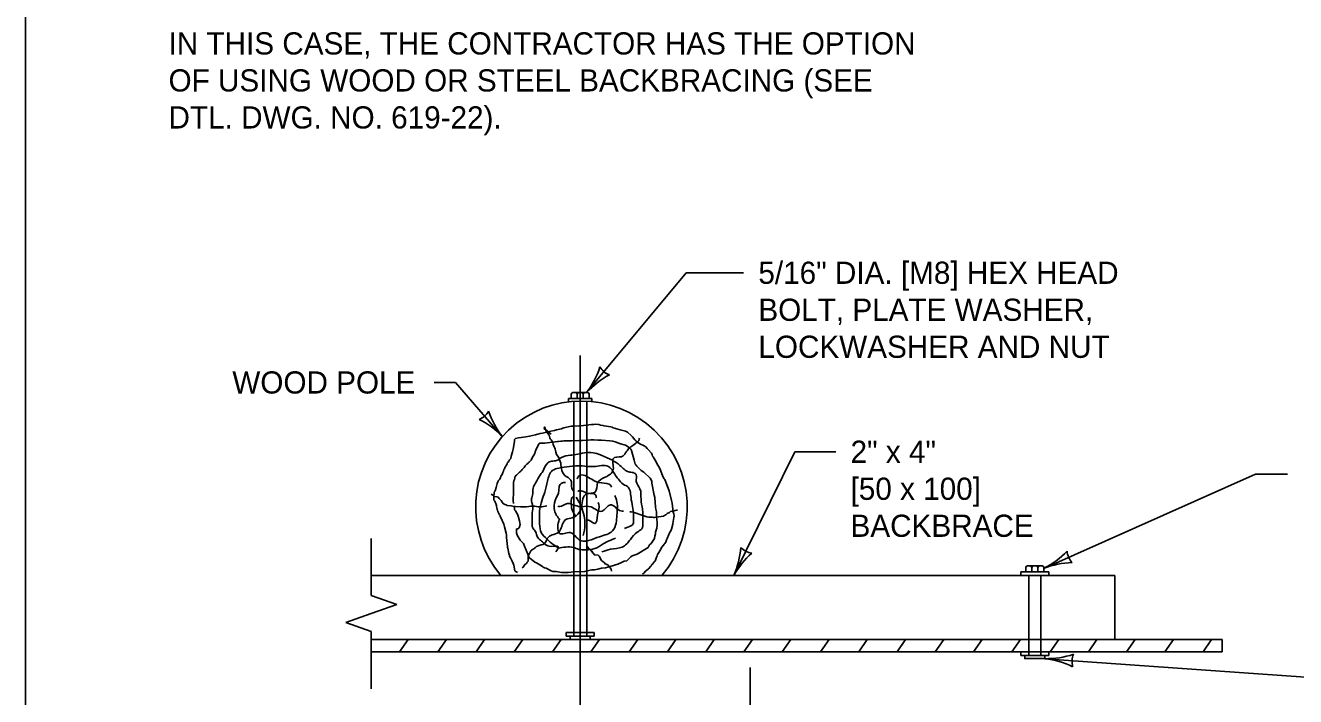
# Model space of a CAD drawing. Extents: x 49991.4 to 50021, y 49987.6 to 50011.4.
# Drawn here: x 50000.336 to 50003.769, y 50005.439 to 50007.252 of the extents above; entities that cross this region are included whole.
import ezdxf

# ---------------------------------------------------------------- set-up
doc = ezdxf.new("R2010")
doc.units = 0
for name, color, linetype in [('Level 1', 7, 'Continuous'), ('Level 2', 7, 'Continuous'), ('Level 3', 7, 'Continuous'), ('Level 4', 7, 'Continuous'), ('Level 5', 7, 'Continuous'), ('Level 6', 7, 'Continuous')]:
    doc.layers.add(name, color=color, linetype=linetype)

msp = doc.modelspace()

# ---------------------------------------------------------------- linework, layer by layer
at = {"layer": 'Level 1'}
for p, q in [((50001.8109, 50006.2555), (50001.8109, 50006.2437)), ((50001.8555, 50006.2601), (50001.8155, 50006.2601)), ((50001.8273, 50006.2601), (50001.8273, 50006.2437)), ((50001.8436, 50006.2601), (50001.8436, 50006.2437)), ((50001.8598, 50006.2554), (50001.8598, 50006.2437)), ((50001.8036, 50006.2437), (50001.8672, 50006.2437)), ((50001.8036, 50006.2437), (50001.8036, 50006.2351)), ((50001.8672, 50006.2357), (50001.8672, 50006.2437)), ((50001.8393, 50005.951), (50001.8245, 50005.9776)), ((50003.0268, 50005.7755), (50003.102, 50005.7755)), ((50003.0268, 50005.7656), (50003.0268, 50005.7755)), ((50003.0398, 50005.7873), (50003.0398, 50005.7755)), ((50003.0844, 50005.7919), (50003.0444, 50005.7919)), ((50003.0562, 50005.7919), (50003.0562, 50005.7755)), ((50003.0725, 50005.7919), (50003.0725, 50005.7755)), ((50003.0887, 50005.7872), (50003.0887, 50005.7755)), ((50003.102, 50005.7656), (50003.102, 50005.7755)), ((50001.2707, 50005.7656), (50003.2808, 50005.7656)), ((50003.2808, 50005.7656), (50003.2808, 50005.593)), ((50001.7978, 50005.6116), (50001.7978, 50005.6015)), ((50001.873, 50005.6116), (50001.7978, 50005.6116)), ((50001.873, 50005.6015), (50001.7978, 50005.6015)), ((50001.873, 50005.6116), (50001.873, 50005.6015)), ((50001.2707, 50005.593), (50003.5711, 50005.593)), ((50001.3468, 50005.5599), (50001.37, 50005.593)), ((50001.4503, 50005.5599), (50001.4735, 50005.593)), ((50001.5537, 50005.5599), (50001.5769, 50005.593)), ((50001.6572, 50005.5599), (50001.6804, 50005.593)), ((50001.7607, 50005.5599), (50001.7839, 50005.593)), ((50001.8641, 50005.5599), (50001.8873, 50005.593)), ((50001.9676, 50005.5599), (50001.9908, 50005.593)), ((50002.071, 50005.5599), (50002.0942, 50005.593)), ((50002.1745, 50005.5599), (50002.1977, 50005.593)), ((50002.2779, 50005.5599), (50002.3011, 50005.593)), ((50002.3814, 50005.5599), (50002.4046, 50005.593)), ((50002.4848, 50005.5599), (50002.508, 50005.593)), ((50002.5883, 50005.5599), (50002.6115, 50005.593)), ((50002.6918, 50005.5599), (50002.715, 50005.593)), ((50002.7952, 50005.5599), (50002.8184, 50005.593)), ((50002.8987, 50005.5599), (50002.9219, 50005.593)), ((50003.0021, 50005.5599), (50003.0253, 50005.593)), ((50003.1056, 50005.5599), (50003.1288, 50005.593)), ((50003.209, 50005.5599), (50003.2322, 50005.593)), ((50003.3125, 50005.5599), (50003.3354, 50005.5925)), ((50003.4159, 50005.5599), (50003.4388, 50005.5925)), ((50003.5194, 50005.5599), (50003.5423, 50005.5925)), ((50003.5711, 50005.5599), (50003.5711, 50005.593)), ((50001.2707, 50005.5599), (50003.5711, 50005.5599)), ((50003.0268, 50005.5599), (50003.0268, 50005.5498)), ((50003.102, 50005.5498), (50003.0268, 50005.5498)), ((50003.102, 50005.5599), (50003.102, 50005.5498))]:
    msp.add_line(p, q, dxfattribs=at)
for points in [[(50008.6146, 50011.2628), (50000.3356, 50011.2628), (50000.3356, 50000.0624), (50008.6146, 50000.0624)], [(50001.8081, 50005.6015), (50001.8081, 50005.593), (50001.8627, 50005.593), (50001.8627, 50005.6015)], [(50003.0371, 50005.5498), (50003.0371, 50005.5413), (50003.0917, 50005.5413), (50003.0917, 50005.5498)]]:
    msp.add_lwpolyline(points, close=True, dxfattribs=at)
for points in [[(50001.6079, 50006.0034), (50001.6112, 50006.0141), (50001.6128, 50006.019), (50001.6145, 50006.0223), (50001.6169, 50006.0256), (50001.6202, 50006.0297), (50001.6211, 50006.0346), (50001.6243, 50006.0387), (50001.626, 50006.0444), (50001.6276, 50006.0477), (50001.6293, 50006.0526), (50001.6309, 50006.0543), (50001.6326, 50006.0592), (50001.6342, 50006.0608), (50001.6375, 50006.0674), (50001.6392, 50006.0707), (50001.6408, 50006.0723), (50001.6425, 50006.0748), (50001.6441, 50006.078), (50001.6474, 50006.0821), (50001.649, 50006.0887), (50001.6523, 50006.1002), (50001.654, 50006.1068), (50001.6573, 50006.1281), (50001.6581, 50006.133), (50001.6606, 50006.1363), (50001.6688, 50006.1379), (50001.6754, 50006.1387), (50001.6886, 50006.1404), (50001.6984, 50006.142), (50001.7149, 50006.1461), (50001.7174, 50006.1469), (50001.7207, 50006.1478), (50001.7273, 50006.1494), (50001.733, 50006.1502), (50001.7445, 50006.1535), (50001.7561, 50006.156), (50001.7659, 50006.1576), (50001.7717, 50006.1592), (50001.7799, 50006.1609), (50001.7849, 50006.1625), (50001.7882, 50006.1642), (50001.7915, 50006.165), (50001.803, 50006.1674), (50001.8112, 50006.1691), (50001.8195, 50006.1691), (50001.8326, 50006.1699), (50001.8442, 50006.1707), (50001.8656, 50006.174), (50001.8721, 50006.174), (50001.8771, 50006.1748), (50001.8853, 50006.174), (50001.8903, 50006.1724), (50001.8968, 50006.1715), (50001.9001, 50006.1699), (50001.9183, 50006.1674), (50001.9215, 50006.1666), (50001.9248, 50006.165), (50001.9438, 50006.1592), (50001.9578, 50006.156), (50001.9611, 50006.1543), (50001.9635, 50006.1527), (50001.9734, 50006.1445), (50001.9751, 50006.142), (50001.9767, 50006.1404), (50001.9833, 50006.1322), (50001.9866, 50006.1289), (50001.9907, 50006.1256), (50001.9981, 50006.1207), (50002.0063, 50006.1174), (50002.0129, 50006.1133), (50002.0162, 50006.1092), (50002.0195, 50006.1059), (50002.0277, 50006.0961), (50002.0302, 50006.092), (50002.031, 50006.0887), (50002.0327, 50006.0862), (50002.0409, 50006.0731), (50002.0442, 50006.0649), (50002.0475, 50006.06), (50002.0524, 50006.0502), (50002.0557, 50006.0403), (50002.0599, 50006.0313), (50002.0623, 50006.0272), (50002.064, 50006.0256), (50002.0714, 50006.0059), (50002.0755, 50005.9944), (50002.0821, 50005.9681), (50002.0837, 50005.9616), (50002.087, 50005.937), (50002.0887, 50005.9321), (50002.0895, 50005.9271), (50002.0887, 50005.9222), (50002.0854, 50005.9066), (50002.0854, 50005.9042), (50002.0821, 50005.891), (50002.0813, 50005.8886), (50002.0788, 50005.8837), (50002.0771, 50005.8812), (50002.0755, 50005.8787), (50002.0747, 50005.8763)], [(50001.7717, 50006.0924), (50001.7692, 50006.0994), (50001.7684, 50006.1035), (50001.7676, 50006.1068), (50001.7668, 50006.11), (50001.7651, 50006.1133), (50001.7627, 50006.1199), (50001.761, 50006.1248), (50001.7594, 50006.1289), (50001.7569, 50006.1322), (50001.7544, 50006.1355), (50001.7536, 50006.1379), (50001.7511, 50006.1453), (50001.747, 50006.1502), (50001.7445, 50006.1535), (50001.7437, 50006.156), (50001.7412, 50006.1609), (50001.7404, 50006.1633), (50001.7396, 50006.1674), (50001.7396, 50006.1674), (50001.738, 50006.1658), (50001.7388, 50006.1609), (50001.7412, 50006.1601), (50001.7569, 50006.1478)], [(50001.6548, 50005.9599), (50001.654, 50005.9681), (50001.654, 50005.9731), (50001.6548, 50005.9878), (50001.6548, 50005.9977), (50001.6548, 50006.0108), (50001.6548, 50006.0174), (50001.6556, 50006.0215), (50001.6573, 50006.0256), (50001.6597, 50006.0338), (50001.663, 50006.037), (50001.6647, 50006.0387), (50001.668, 50006.0411), (50001.6696, 50006.0436), (50001.6713, 50006.0452), (50001.6737, 50006.0469), (50001.6754, 50006.0485), (50001.6787, 50006.0526), (50001.6812, 50006.0551), (50001.6836, 50006.0575), (50001.6869, 50006.0625), (50001.691, 50006.0666), (50001.6943, 50006.069), (50001.696, 50006.0707), (50001.6976, 50006.0723), (50001.7009, 50006.0756), (50001.7026, 50006.0772), (50001.7058, 50006.0838), (50001.7124, 50006.0953), (50001.7133, 50006.1002), (50001.7166, 50006.1068), (50001.7207, 50006.115), (50001.7231, 50006.1215), (50001.7256, 50006.1232), (50001.733, 50006.1232), (50001.7396, 50006.1232), (50001.7462, 50006.124), (50001.7528, 50006.1248), (50001.761, 50006.1264), (50001.7742, 50006.1281), (50001.7766, 50006.1281), (50001.7832, 50006.1289), (50001.7865, 50006.1289), (50001.7915, 50006.1297), (50001.8055, 50006.1297), (50001.8088, 50006.1297), (50001.8121, 50006.1297), (50001.8318, 50006.1305), (50001.8417, 50006.1305), (50001.8516, 50006.1314), (50001.8565, 50006.1314), (50001.8639, 50006.1322), (50001.8721, 50006.1322), (50001.8829, 50006.1314), (50001.8861, 50006.1314), (50001.8927, 50006.1314), (50001.915, 50006.1297), (50001.9232, 50006.1289), (50001.9298, 50006.1273), (50001.9446, 50006.1215), (50001.9578, 50006.1182), (50001.9676, 50006.1117), (50001.9718, 50006.1068), (50001.9742, 50006.1035), (50001.9816, 50006.0772), (50001.9841, 50006.0666), (50001.9858, 50006.0649), (50001.9882, 50006.0616), (50001.9965, 50006.0534), (50001.9998, 50006.0493), (50002.0072, 50006.0452), (50002.0245, 50006.0288), (50002.0286, 50006.0206), (50002.0294, 50006.0157), (50002.0352, 50005.9829), (50002.0368, 50005.9763), (50002.0385, 50005.9501), (50002.0401, 50005.9452), (50002.0417, 50005.9378), (50002.0417, 50005.9247), (50002.0434, 50005.9099), (50002.0434, 50005.9033), (50002.0426, 50005.8935), (50002.0409, 50005.8886), (50002.0393, 50005.8828), (50002.0385, 50005.8787), (50002.0368, 50005.8722), (50002.036, 50005.8656), (50002.0269, 50005.8525), (50002.0228, 50005.8484), (50002.0212, 50005.8451), (50002.0187, 50005.8418), (50001.9891, 50005.8238), (50001.9759, 50005.8189), (50001.9726, 50005.8164), (50001.9701, 50005.8148), (50001.9611, 50005.8057), (50001.9545, 50005.8041), (50001.9438, 50005.7992), (50001.9405, 50005.7984), (50001.9372, 50005.7967)], [(50001.9471, 50006.0865), (50001.9495, 50006.0879), (50001.9512, 50006.0895), (50001.9545, 50006.092), (50001.9561, 50006.0936), (50001.9578, 50006.0977), (50001.9594, 50006.1002), (50001.9627, 50006.1027), (50001.9644, 50006.1051), (50001.966, 50006.1084), (50001.9685, 50006.11), (50001.9701, 50006.1117), (50001.9726, 50006.1133), (50001.9751, 50006.115), (50001.9775, 50006.1174), (50001.9816, 50006.1199), (50001.9849, 50006.1223), (50001.9866, 50006.124), (50001.9891, 50006.1256), (50001.9915, 50006.1281), (50001.994, 50006.1305), (50001.9948, 50006.1346), (50001.9956, 50006.1371)], [(50001.6795, 50005.9515), (50001.6737, 50005.9509), (50001.6606, 50005.9526), (50001.6523, 50005.9534), (50001.6482, 50005.9542), (50001.6383, 50005.955), (50001.635, 50005.9567), (50001.6318, 50005.9575), (50001.6268, 50005.9599), (50001.6243, 50005.964), (50001.6219, 50005.9681), (50001.6186, 50005.9714), (50001.6161, 50005.9739), (50001.6136, 50005.9772), (50001.6103, 50005.9788), (50001.6038, 50005.9796), (50001.6021, 50005.9813), (50001.5988, 50005.9829), (50001.5947, 50005.9854)], [(50001.6079, 50006.0034), (50001.6054, 50005.9944), (50001.6038, 50005.9927), (50001.6029, 50005.9895), (50001.6021, 50005.9796), (50001.6021, 50005.9731), (50001.6021, 50005.969), (50001.6046, 50005.9665), (50001.6054, 50005.964), (50001.6071, 50005.9599), (50001.6087, 50005.955), (50001.6087, 50005.9526), (50001.6103, 50005.9485), (50001.6112, 50005.9444), (50001.612, 50005.9419), (50001.6128, 50005.9386), (50001.6145, 50005.9353), (50001.6169, 50005.9296), (50001.6186, 50005.928), (50001.6194, 50005.9255), (50001.6211, 50005.9222), (50001.6285, 50005.9042), (50001.6309, 50005.8976), (50001.635, 50005.8804), (50001.6359, 50005.8755), (50001.6359, 50005.8689), (50001.6392, 50005.8443), (50001.6392, 50005.8418), (50001.64, 50005.8394), (50001.6425, 50005.8254), (50001.6441, 50005.8205), (50001.6441, 50005.818), (50001.6466, 50005.8131), (50001.6507, 50005.8066), (50001.6515, 50005.8041), (50001.654, 50005.7984), (50001.6556, 50005.7934), (50001.6589, 50005.7787), (50001.6606, 50005.7762), (50001.663, 50005.7754), (50001.6655, 50005.7738)], [(50001.9372, 50005.7967), (50001.9166, 50005.7902), (50001.91, 50005.7885), (50001.9034, 50005.7861), (50001.8927, 50005.7852), (50001.8829, 50005.7828), (50001.8738, 50005.7811), (50001.8672, 50005.7811), (50001.854, 50005.7787), (50001.8475, 50005.777), (50001.8178, 50005.7754), (50001.803, 50005.7738), (50001.7964, 50005.7738), (50001.7849, 50005.7738), (50001.7701, 50005.7762), (50001.7618, 50005.777), (50001.7569, 50005.7787), (50001.7437, 50005.7852), (50001.7388, 50005.7861), (50001.7355, 50005.7885), (50001.7338, 50005.7902), (50001.7264, 50005.7943), (50001.7174, 50005.8), (50001.7124, 50005.8016), (50001.6984, 50005.8131), (50001.6951, 50005.8189), (50001.6935, 50005.8238), (50001.6844, 50005.8451), (50001.682, 50005.8525), (50001.6795, 50005.855), (50001.6729, 50005.8615), (50001.6647, 50005.8746), (50001.663, 50005.8812), (50001.663, 50005.891), (50001.6688, 50005.8927), (50001.6704, 50005.8943), (50001.6729, 50005.9033), (50001.6721, 50005.9074), (50001.6713, 50005.9132), (50001.6696, 50005.9198), (50001.6672, 50005.9263), (50001.6655, 50005.9312), (50001.6639, 50005.9345), (50001.6606, 50005.9403), (50001.6581, 50005.9435), (50001.6573, 50005.9476), (50001.6565, 50005.9501)], [(50002.0335, 50005.9229), (50002.0368, 50005.9222), (50002.0475, 50005.9247), (50002.0607, 50005.9263), (50002.0631, 50005.928), (50002.0664, 50005.9296), (50002.0689, 50005.9312), (50002.0706, 50005.9337), (50002.0763, 50005.9362), (50002.0796, 50005.9386), (50002.0829, 50005.9394), (50002.0878, 50005.9394), (50002.092, 50005.9411), (50002.0953, 50005.9419), (50002.0985, 50005.9419)], [(50002.0747, 50005.8763), (50002.0706, 50005.8656), (50002.0689, 50005.8623), (50002.0673, 50005.8599), (50002.0673, 50005.8574), (50002.064, 50005.8525), (50002.0623, 50005.85), (50002.0607, 50005.8476), (50002.0549, 50005.841), (50002.0533, 50005.8369), (50002.0475, 50005.8279), (50002.0442, 50005.8221), (50002.0434, 50005.8189), (50002.0417, 50005.8156), (50002.0376, 50005.8049), (50002.036, 50005.8033), (50002.031, 50005.7967), (50002.0294, 50005.7951), (50002.0269, 50005.7918), (50002.0253, 50005.7902), (50002.0212, 50005.7844), (50002.0195, 50005.7828), (50002.0154, 50005.7803), (50002.0121, 50005.7779), (50002.008, 50005.7729), (50002.0039, 50005.7697)], [(50001.7102, 50005.8378), (50001.7034, 50005.8345), (50001.7017, 50005.832), (50001.6984, 50005.8254), (50001.6968, 50005.8221), (50001.6951, 50005.8164), (50001.6951, 50005.8115), (50001.6943, 50005.8049), (50001.6919, 50005.8016), (50001.6902, 50005.7984), (50001.6877, 50005.7967), (50001.6853, 50005.7951), (50001.6828, 50005.791), (50001.6812, 50005.7885), (50001.6787, 50005.7869)], [(50001.8661, 50005.8319), (50001.8738, 50005.8213), (50001.8837, 50005.8205), (50001.887, 50005.818), (50001.8894, 50005.8139), (50001.8911, 50005.809), (50001.8927, 50005.8066), (50001.8944, 50005.8049), (50001.8968, 50005.8033), (50001.901, 50005.8), (50001.9026, 50005.7975), (50001.91, 50005.7943), (50001.9125, 50005.791), (50001.915, 50005.7885), (50001.9166, 50005.7861), (50001.9191, 50005.7828), (50001.9199, 50005.7779)]]:
    msp.add_lwpolyline(points, dxfattribs=at)
for centre, radius, start, end in [((50001.8155, 50006.2555), 0.00457, 90, 180), ((50001.8227, 50006.2555), 0.00457, 0, 90), ((50001.8319, 50006.2555), 0.00457, 90, 180), ((50001.8391, 50006.2555), 0.00457, 0, 90), ((50001.8482, 50006.2555), 0.00457, 90, 180), ((50001.8552, 50006.2554), 0.00457, 0, 90), ((50001.8386, 50005.9513), 0.2859, 319.4408, 220.5003), ((50003.0444, 50005.7873), 0.00457, 90, 180), ((50003.0516, 50005.7873), 0.00457, 0, 90), ((50003.0608, 50005.7873), 0.00457, 90, 180), ((50003.068, 50005.7873), 0.00457, 0, 90), ((50003.0771, 50005.7873), 0.00457, 90, 180), ((50003.0841, 50005.7872), 0.00457, 0, 90)]:
    msp.add_arc(centre, radius, start, end, dxfattribs=at)
for points in [[(50001.739, 50005.8514), (50001.728, 50005.8613), (50001.7191, 50005.871), (50001.7153, 50005.8829), (50001.7083, 50005.8927), (50001.7055, 50005.9005), (50001.7055, 50005.9171), (50001.7055, 50005.9348), (50001.7066, 50005.9572), (50001.7035, 50005.9692), (50001.7066, 50005.9829), (50001.7083, 50006.0015), (50001.7153, 50006.0172), (50001.7261, 50006.0358), (50001.734, 50006.0465), (50001.7476, 50006.0702), (50001.7583, 50006.0749), (50001.7713, 50006.0761), (50001.785, 50006.085), (50001.8094, 50006.0908), (50001.8232, 50006.0927), (50001.8701, 50006.0975), (50001.8898, 50006.0916), (50001.9222, 50006.0771), (50001.9429, 50006.0632), (50001.9665, 50006.0457), (50001.979, 50006.0437), (50001.9869, 50006.0378), (50001.9869, 50006.0201), (50001.9968, 50006.0004), (50001.9997, 50005.9721), (50002.0036, 50005.9446), (50002.0046, 50005.9094), (50002.0018, 50005.8918), (50001.989, 50005.8829), (50001.9712, 50005.8632), (50001.9487, 50005.8426), (50001.9173, 50005.8367), (50001.8941, 50005.8294)], [(50001.8159, 50005.9947), (50001.8129, 50006.0012), (50001.81, 50006.0238), (50001.7934, 50006.0364), (50001.7845, 50006.0552), (50001.7816, 50006.0738), (50001.7717, 50006.0924)], [(50001.8393, 50005.951), (50001.8532, 50005.9864), (50001.8757, 50005.9914), (50001.8825, 50006.0159), (50001.9032, 50006.0316), (50001.9247, 50006.0522), (50001.9247, 50006.0815), (50001.9482, 50006.0866)], [(50001.7796, 50005.8394), (50001.7639, 50005.8482), (50001.7454, 50005.8648), (50001.7306, 50005.8806), (50001.7256, 50005.9052), (50001.7256, 50005.9403), (50001.7315, 50005.9677), (50001.7395, 50005.9914), (50001.7472, 50006.0208), (50001.76, 50006.0493), (50001.7777, 50006.0561), (50001.806, 50006.0602), (50001.8404, 50006.0621), (50001.8718, 50006.0602), (50001.9121, 50006.0602), (50001.9238, 50006.0481), (50001.9306, 50006.0364), (50001.9413, 50006.0227), (50001.9552, 50006.0101), (50001.962, 50006.0071), (50001.9727, 50005.9766), (50001.9768, 50005.9521), (50001.9797, 50005.9306), (50001.9797, 50005.917), (50001.9786, 50005.9052), (50001.9638, 50005.8963), (50001.955, 50005.8931)], [(50001.7805, 50005.9159), (50001.7657, 50005.9414), (50001.7679, 50005.9687), (50001.7777, 50005.9953), (50001.7796, 50006.0091), (50001.7904, 50006.0169), (50001.7952, 50006.0172)], [(50001.8269, 50006.0271), (50001.8326, 50006.0355), (50001.8668, 50006.0257), (50001.8934, 50006.0159), (50001.9179, 50006.0091), (50001.9195, 50006.0047)], [(50001.9287, 50005.9821), (50001.9336, 50005.97), (50001.9345, 50005.9286), (50001.9324, 50005.9071), (50001.9228, 50005.8863), (50001.8874, 50005.8707), (50001.8326, 50005.862), (50001.8247, 50005.8698), (50001.808, 50005.8816), (50001.7796, 50005.8796), (50001.7746, 50005.8971), (50001.7787, 50005.917)], [(50001.8187, 50005.9818), (50001.8139, 50005.9766), (50001.811, 50005.96), (50001.8159, 50005.9375), (50001.8228, 50005.9278)], [(50001.8794, 50005.9756), (50001.8766, 50005.9835), (50001.855, 50005.9883), (50001.8296, 50005.9934), (50001.8291, 50005.9929)], [(50001.7455, 50005.9544), (50001.7265, 50005.951), (50001.7081, 50005.9531), (50001.6844, 50005.951), (50001.6767, 50005.9521)], [(50001.7099, 50005.8374), (50001.7199, 50005.8453), (50001.7384, 50005.8521), (50001.7492, 50005.8698), (50001.7639, 50005.8767), (50001.7805, 50005.8863), (50001.7824, 50005.8904), (50001.798, 50005.9178), (50001.8139, 50005.9217), (50001.8326, 50005.9364), (50001.8393, 50005.951)], [(50001.8393, 50005.951), (50001.8217, 50005.9551), (50001.8013, 50005.96), (50001.7796, 50005.9521), (50001.775, 50005.9529)], [(50001.8393, 50005.951), (50001.8649, 50005.951), (50001.8943, 50005.9395), (50001.9169, 50005.9569), (50001.9453, 50005.9403), (50001.952, 50005.9397)], [(50001.8393, 50005.951), (50001.8482, 50005.9031), (50001.8437, 50005.8738)], [(50001.852, 50005.9165), (50001.861, 50005.9139), (50001.8748, 50005.906), (50001.8825, 50005.9295), (50001.8855, 50005.9581), (50001.8838, 50005.9627)], [(50001.9696, 50005.9378), (50001.9727, 50005.9375), (50001.9942, 50005.9315), (50002.0159, 50005.9246), (50002.0357, 50005.9228)], [(50001.7694, 50005.8294), (50001.7761, 50005.8436), (50001.7516, 50005.8446), (50001.7378, 50005.8525)], [(50001.9305, 50005.8664), (50001.8973, 50005.8512), (50001.8748, 50005.8383), (50001.8501, 50005.8353), (50001.8316, 50005.8364), (50001.8168, 50005.8413), (50001.7756, 50005.8394)], [(50001.8532, 50005.8455), (50001.864, 50005.8335), (50001.8696, 50005.8294)]]:
    msp.add_spline(points, degree=3, dxfattribs=at)
at = {"layer": 'Level 3'}
for p, q in [((50001.8527, 50006.2601), (50002.1222, 50006.5839)), ((50002.1222, 50006.5839), (50002.277, 50006.5839)), ((50001.4406, 50006.2875), (50001.4985, 50006.2875)), ((50001.4985, 50006.2875), (50001.6248, 50006.1412)), ((50002.4151, 50006.1002), (50002.2507, 50005.7656)), ((50002.5262, 50006.1002), (50002.4151, 50006.1002)), ((50003.6606, 50006.0398), (50003.0887, 50005.7851)), ((50003.7476, 50006.0398), (50003.6606, 50006.0398)), ((50003.0917, 50005.541), (50003.8659, 50005.4865))]:
    msp.add_line(p, q, dxfattribs=at)
for centre, radius, start, end in [((50001.6665, 50006.4001), 0.233, 323.0566, 342.3064), ((50001.9347, 50006.3586), 0.0548, 212.3681, 248.0904), ((50002.0176, 50006.111), 0.2223, 117.6853, 137.8688), ((50001.541, 50006.2382), 0.0548, 292.9427, 328.665), ((50001.4562, 50005.9804), 0.233, 43.6312, 62.881), ((50001.799, 50006.2794), 0.2223, 198.2599, 218.4434), ((50002.0368, 50005.858), 0.233, 336.6453, 355.8951), ((50002.3073, 50005.8807), 0.0548, 225.9568, 261.6791), ((50002.446, 50005.6594), 0.2223, 131.274, 151.4575), ((50002.9836, 50005.9931), 0.233, 296.8165, 316.0663), ((50003.2058, 50005.8373), 0.0548, 186.128, 221.8503), ((50003.1706, 50005.5785), 0.2223, 91.4452, 111.6287), ((50003.0952, 50005.774), 0.233, 269.1467, 288.3966), ((50003.0683, 50005.3199), 0.2223, 63.7754, 83.9589), ((50003.2197, 50005.5328), 0.0548, 158.4582, 194.1806)]:
    msp.add_arc(centre, radius, start, end, dxfattribs=at)
at = {"layer": 'Level 4'}
for p, q in [((50001.8179, 50005.6015), (50001.8179, 50006.2364)), ((50001.8529, 50005.6015), (50001.8529, 50006.2368)), ((50003.0484, 50005.7656), (50003.0484, 50005.5498)), ((50003.0804, 50005.7656), (50003.0804, 50005.5498))]:
    msp.add_line(p, q, dxfattribs=at)
at = {"layer": 'Level 5'}
msp.add_line((50001.8354, 50004.2009), (50001.8354, 50006.3601), dxfattribs=at)
at = {"layer": 'Level 6'}
for p, q in [((50001.2707, 50005.8656), (50001.2707, 50005.7114)), ((50001.3393, 50005.6871), (50001.2707, 50005.7114)), ((50001.3393, 50005.6871), (50001.2707, 50005.6628)), ((50001.2707, 50005.6628), (50001.2021, 50005.6385)), ((50001.2707, 50005.6142), (50001.2021, 50005.6385)), ((50001.2707, 50005.6142), (50001.2707, 50005.4599)), ((50002.2949, 50005.5172), (50002.2949, 50005.1746))]:
    msp.add_line(p, q, dxfattribs=at)

# ---------------------------------------------------------------- texts
at = {"layer": 'Level 2'}
for s, p in [('IN THIS CASE, THE CONTRACTOR HAS THE OPTION', (50000.7225, 50007.1737)), ('OF USING WOOD OR STEEL BACKBRACING (SEE', (50000.7225, 50007.0737)), ('DTL. DWG. NO. 619-22).', (50000.7225, 50006.9737)), ('5/16" DIA. [M8] HEX HEAD', (50002.317, 50006.5539)), ('BOLT, PLATE WASHER,', (50002.317, 50006.4539)), ('LOCKWASHER AND NUT', (50002.317, 50006.3539)), ('WOOD POLE', (50000.8949, 50006.2575)), ('2" x 4"', (50002.5662, 50006.0702)), ('[50 x 100]', (50002.5662, 50005.9702)), ('BACKBRACE', (50002.5662, 50005.8702))]:
    msp.add_text(s, height=0.06, dxfattribs=at).set_placement(p)

doc.saveas('drawing.dxf')
